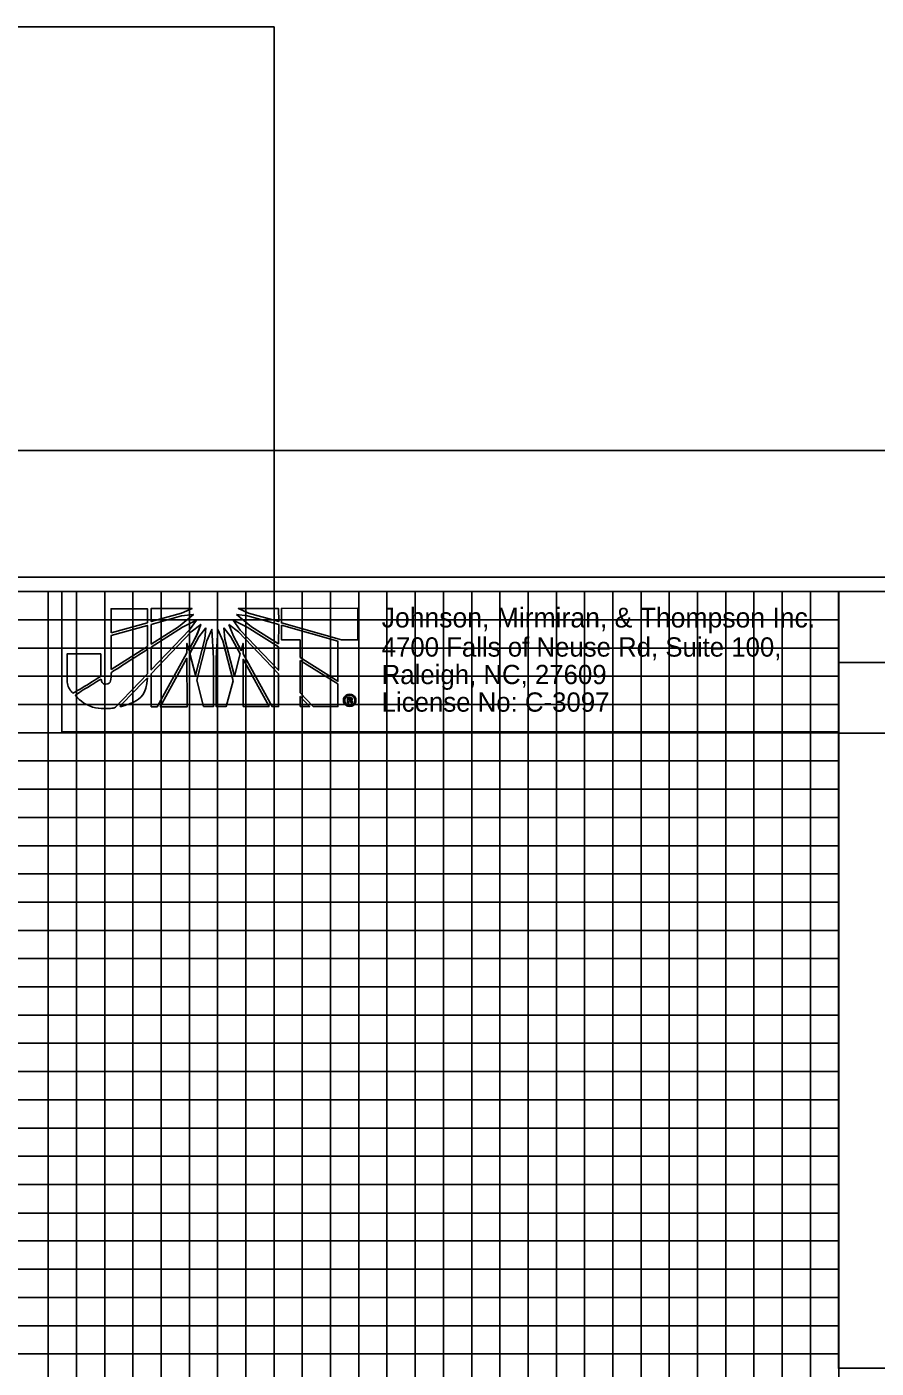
# Model space of a CAD drawing. Extents: x 1621288 to 1629363, y 896995 to 899414.
# Drawn here: x 1628625.6 to 1628776, y 897932.1 to 898169.7 of the extents above; entities that cross this region are included whole.
import ezdxf

# ---------------------------------------------------------------- set-up
doc = ezdxf.new("R2010")
doc.units = 0
for name, color, linetype in [('Default', 7, 'Continuous'), ('Exist Profile Cell', 7, 'Continuous'), ('Exist Structure Minor Pipes CMAP 112inx75in', 7, 'Continuous'), ('Exist Vertical Profile Horizontal Axis Label Major', 7, 'Continuous'), ('Exist XS Ground Line', 7, 'Continuous'), ('Prop Vertical Profile Curve Label', 7, 'Continuous'), ('Prop Vertical Profile Grade', 7, 'Continuous'), ('Prop VPI Label', 7, 'Continuous'), ('Sheet Layout Plan Border', 7, 'Continuous'), ('Sheet Layout Profile Border', 7, 'Continuous'), ('Sheet Layout Profile Border Port 2', 7, 'Continuous')]:
    doc.layers.add(name, color=color, linetype=linetype)

msp = doc.modelspace()

# ---------------------------------------------------------------- linework, layer by layer
at = {"layer": 'Default'}
for p, q in [((1628646.95, 898066.62), (1628640.51, 898066.62)), ((1628640.51, 898066.62), (1628640.51, 898062.35)), ((1628646.95, 898064.14), (1628646.95, 898066.62)), ((1628654.86, 898066.66), (1628647.61, 898066.65)), ((1628647.61, 898066.65), (1628647.62, 898064.35)), ((1628647.62, 898064.35), (1628653.01, 898065.84)), ((1628652.45, 898063.43), (1628655.11, 898065.6)), ((1628653.01, 898065.84), (1628654.86, 898066.66)), ((1628655.11, 898065.6), (1628653.01, 898065.34)), ((1628662.7, 898065.6), (1628665.4, 898063.4)), ((1628664.68, 898065.35), (1628662.7, 898065.6)), ((1628670.19, 898066.64), (1628663.06, 898066.67)), ((1628663.06, 898066.67), (1628664.86, 898065.82)), ((1628664.86, 898065.82), (1628670.2, 898064.33)), ((1628670.2, 898064.33), (1628670.19, 898066.64)), ((1628684.22, 898066.69), (1628670.69, 898066.67)), ((1628670.69, 898066.67), (1628670.69, 898064.19)), ((1628684.23, 898061.14), (1628684.22, 898066.69)), ((1628640.51, 898062.35), (1628646.95, 898064.14)), ((1628646.95, 898063.67), (1628640.51, 898061.86)), ((1628646.95, 898059.94), (1628646.95, 898063.67)), ((1628653.01, 898065.34), (1628647.62, 898063.85)), ((1628647.62, 898063.85), (1628647.62, 898060.37)), ((1628647.62, 898060.37), (1628652.45, 898063.43)), ((1628653.19, 898063.36), (1628647.62, 898059.8)), ((1628655.65, 898064.6), (1628653.19, 898063.36)), ((1628654.4, 898062.86), (1628655.65, 898064.6)), ((1628656.39, 898063.83), (1628654.68, 898062.51)), ((1628655.61, 898061.76), (1628656.39, 898063.83)), ((1628657.31, 898063.25), (1628656.04, 898061.62)), ((1628657.13, 898061.27), (1628657.31, 898063.25)), ((1628660.47, 898063.26), (1628660.68, 898061.2)), ((1628661.71, 898061.62), (1628660.47, 898063.26)), ((1628661.38, 898063.83), (1628662.17, 898061.77)), ((1628663.09, 898062.51), (1628661.38, 898063.83)), ((1628662.13, 898064.61), (1628663.38, 898062.83)), ((1628664.62, 898063.37), (1628662.13, 898064.61)), ((1628670.16, 898059.85), (1628664.62, 898063.37)), ((1628670.2, 898063.84), (1628664.68, 898065.35)), ((1628665.4, 898063.4), (1628670.16, 898060.43)), ((1628670.16, 898060.43), (1628670.2, 898063.84)), ((1628670.69, 898064.19), (1628670.69, 898064.11)), ((1628670.69, 898064.11), (1628681.35, 898061.14)), ((1628670.69, 898063.73), (1628670.69, 898063.69)), ((1628680.67, 898060.89), (1628670.69, 898063.73)), ((1628670.69, 898063.69), (1628670.7, 898061.1)), ((1628640.51, 898061.86), (1628640.52, 898055.86)), ((1628647.62, 898055.79), (1628654.4, 898062.86)), ((1628654.68, 898062.51), (1628647.62, 898055.11)), ((1628654.26, 898059.31), (1628655.61, 898061.76)), ((1628656.04, 898061.62), (1628654.44, 898058.71)), ((1628655.47, 898054.84), (1628657.13, 898061.27)), ((1628657.5, 898060.91), (1628655.69, 898053.95)), ((1628658.38, 898062.97), (1628657.5, 898060.91)), ((1628658.66, 898057.89), (1628658.38, 898062.97)), ((1628659.44, 898062.97), (1628659.11, 898057.89)), ((1628660.29, 898060.91), (1628659.44, 898062.97)), ((1628662.14, 898053.85), (1628660.29, 898060.91)), ((1628660.68, 898061.2), (1628662.35, 898054.7)), ((1628663.38, 898058.61), (1628661.71, 898061.62)), ((1628662.17, 898061.77), (1628663.55, 898059.21)), ((1628670.16, 898055.07), (1628663.09, 898062.51)), ((1628663.38, 898062.83), (1628670.16, 898055.73)), ((1628670.7, 898061.1), (1628674, 898061.1)), ((1628674, 898061.1), (1628674, 898058.01)), ((1628680.68, 898053.79), (1628680.67, 898060.89)), ((1628681.35, 898061.14), (1628684.23, 898061.14)), ((1628640.52, 898055.86), (1628646.95, 898059.94)), ((1628647.62, 898059.8), (1628647.62, 898055.79)), ((1628648.69, 898049.27), (1628653.94, 898058.78)), ((1628653.94, 898058.78), (1628653.94, 898060.48)), ((1628653.94, 898060.48), (1628654.26, 898059.31)), ((1628654.44, 898058.71), (1628655.47, 898054.84)), ((1628662.35, 898054.7), (1628663.38, 898058.61)), ((1628663.55, 898059.21), (1628663.88, 898060.49)), ((1628663.88, 898060.49), (1628663.88, 898058.61)), ((1628663.88, 898058.61), (1628669.03, 898049.29)), ((1628670.16, 898055.73), (1628670.16, 898059.85)), ((1628653.94, 898057.86), (1628649.19, 898049.27)), ((1628653.99, 898049.27), (1628653.94, 898057.86)), ((1628658.66, 898049.31), (1628658.66, 898057.89)), ((1628659.11, 898057.89), (1628659.12, 898049.31)), ((1628668.5, 898049.32), (1628663.88, 898057.68)), ((1628663.88, 898057.68), (1628663.89, 898049.31)), ((1628674, 898058.01), (1628680.68, 898053.79)), ((1628674, 898057.48), (1628674.01, 898051.72)), ((1628680.68, 898053.29), (1628674, 898057.48)), ((1628647.62, 898055.11), (1628647.63, 898049.27)), ((1628655.69, 898053.95), (1628656.9, 898049.31)), ((1628660.9, 898049.31), (1628662.14, 898053.85)), ((1628670.17, 898049.29), (1628670.16, 898055.07)), ((1628674.01, 898051.72), (1628676.31, 898049.29)), ((1628680.68, 898049.3), (1628680.68, 898053.29)), ((1628682.77, 898051.47), (1628682.77, 898051.27)), ((1628682.77, 898051.27), (1628682.77, 898051.47)), ((1628647.63, 898049.27), (1628648.69, 898049.27)), ((1628649.19, 898049.27), (1628653.99, 898049.27)), ((1628656.9, 898049.31), (1628658.66, 898049.31)), ((1628659.12, 898049.31), (1628660.9, 898049.31)), ((1628663.89, 898049.31), (1628668.5, 898049.32)), ((1628669.03, 898049.29), (1628670.17, 898049.29)), ((1628675.68, 898049.29), (1628674.01, 898051.1)), ((1628674.01, 898051.1), (1628674.01, 898049.29)), ((1628674.01, 898049.29), (1628675.68, 898049.29)), ((1628676.31, 898049.29), (1628680.68, 898049.3)), ((1628682.37, 898049.91), (1628682.37, 898050.89)), ((1628682.37, 898050.89), (1628682.78, 898050.89)), ((1628682.6, 898049.91), (1628682.37, 898049.91)), ((1628682.78, 898050.7), (1628682.6, 898050.7)), ((1628682.6, 898050.7), (1628682.6, 898050.47)), ((1628682.6, 898050.47), (1628682.78, 898050.47)), ((1628682.78, 898050.29), (1628682.6, 898050.29)), ((1628682.6, 898050.29), (1628682.6, 898049.91)), ((1628682.78, 898050.89), (1628682.78, 898050.7)), ((1628682.78, 898050.7), (1628682.78, 898050.89)), ((1628682.78, 898050.89), (1628682.84, 898050.89)), ((1628682.8, 898050.7), (1628682.78, 898050.7)), ((1628682.78, 898050.47), (1628682.78, 898050.29)), ((1628682.78, 898050.29), (1628682.78, 898050.47)), ((1628682.78, 898050.47), (1628682.78, 898050.47)), ((1628682.78, 898050.29), (1628682.78, 898050.29)), ((1628682.78, 898049.52), (1628682.78, 898049.31)), ((1628682.78, 898049.31), (1628682.78, 898049.52)), ((1628682.78, 898049.52), (1628682.79, 898049.52)), ((1628682.79, 898049.31), (1628682.78, 898049.31))]:
    msp.add_line(p, q, dxfattribs=at)
for points in [[(1628631.8, 898044.84), (1628769.33, 898044.83), (1628769.33, 898069.65), (1628631.81, 898069.66)], [(1628663.06, 898066.67), (1628670.19, 898066.64), (1628670.2, 898064.33), (1628664.86, 898065.82)], [(1628647.63, 898049.27), (1628647.62, 898055.11), (1628654.68, 898062.51), (1628656.39, 898063.83), (1628655.82, 898062.2), (1628654.26, 898059.31), (1628653.94, 898060.48), (1628653.94, 898058.78), (1628648.69, 898049.27)]]:
    msp.add_lwpolyline(points, close=True, dxfattribs=at)
for points in [[(1628640.51, 898062.35), (1628646.95, 898064.14), (1628646.95, 898066.62), (1628640.51, 898066.62), (1628640.51, 898062.35)], [(1628653.01, 898065.84), (1628654.86, 898066.66), (1628647.61, 898066.65), (1628647.62, 898064.35), (1628653.01, 898065.84)], [(1628647.62, 898063.85), (1628647.62, 898060.37), (1628652.45, 898063.43), (1628655.11, 898065.6), (1628653.01, 898065.34), (1628647.62, 898063.85)], [(1628662.7, 898065.6), (1628665.4, 898063.4), (1628670.16, 898060.43), (1628670.2, 898063.84), (1628664.68, 898065.35), (1628662.7, 898065.6)], [(1628664.86, 898065.82), (1628670.2, 898064.33), (1628670.19, 898066.64), (1628663.06, 898066.67), (1628664.86, 898065.82)], [(1628684.22, 898066.69), (1628670.69, 898066.67), (1628670.69, 898064.19), (1628670.69, 898064.11), (1628681.35, 898061.14), (1628684.23, 898061.14), (1628684.22, 898066.69)], [(1628640.52, 898055.86), (1628646.95, 898059.94), (1628646.95, 898063.67), (1628640.51, 898061.86), (1628640.52, 898055.86)], [(1628647.62, 898059.8), (1628647.62, 898055.79), (1628654.4, 898062.86), (1628655.65, 898064.6), (1628653.19, 898063.36), (1628647.62, 898059.8)], [(1628656.39, 898063.83), (1628654.68, 898062.51), (1628647.62, 898055.11), (1628647.63, 898049.27), (1628648.69, 898049.27), (1628653.94, 898058.78), (1628653.94, 898060.48), (1628654.26, 898059.31), (1628655.61, 898061.76), (1628656.39, 898063.83)], [(1628657.31, 898063.25), (1628656.04, 898061.62), (1628654.44, 898058.71), (1628655.47, 898054.84), (1628657.13, 898061.27), (1628657.31, 898063.25)], [(1628660.47, 898063.26), (1628660.68, 898061.2), (1628662.35, 898054.7), (1628663.38, 898058.61), (1628661.71, 898061.62), (1628660.47, 898063.26)], [(1628661.38, 898063.83), (1628662.17, 898061.77), (1628663.55, 898059.21), (1628663.88, 898060.49), (1628663.88, 898058.61), (1628669.03, 898049.29), (1628670.17, 898049.29), (1628670.16, 898055.07), (1628663.09, 898062.51), (1628661.38, 898063.83)], [(1628662.13, 898064.61), (1628663.38, 898062.83), (1628670.16, 898055.73), (1628670.16, 898059.85), (1628664.62, 898063.37), (1628662.13, 898064.61)], [(1628670.69, 898063.73), (1628670.69, 898063.69), (1628670.7, 898061.1), (1628674, 898061.1), (1628674, 898058.01), (1628680.68, 898053.79), (1628680.67, 898060.89), (1628670.69, 898063.73)], [(1628657.5, 898060.91), (1628655.69, 898053.95), (1628656.9, 898049.31), (1628658.66, 898049.31), (1628658.66, 898057.89), (1628658.38, 898062.97), (1628657.5, 898060.91)], [(1628659.44, 898062.97), (1628659.11, 898057.89), (1628659.12, 898049.31), (1628660.9, 898049.31), (1628662.14, 898053.85), (1628660.29, 898060.91), (1628659.44, 898062.97)], [(1628649.19, 898049.27), (1628653.99, 898049.27), (1628653.94, 898057.86), (1628649.19, 898049.27)], [(1628663.89, 898049.31), (1628668.5, 898049.32), (1628663.88, 898057.68), (1628663.89, 898049.31)], [(1628674, 898057.48), (1628674.01, 898051.72), (1628676.31, 898049.29), (1628680.68, 898049.3), (1628680.68, 898053.29), (1628674, 898057.48), (1628674, 898057.48)], [(1628674.01, 898049.29), (1628674.01, 898049.29), (1628675.68, 898049.29), (1628674.01, 898051.1), (1628674.01, 898049.29)], [(1628683.21, 898050.14), (1628683.21, 898050.09), (1628683.21, 898050.05), (1628683.21, 898050.01), (1628683.24, 898049.91), (1628683.04, 898049.91)]]:
    msp.add_lwpolyline(points, dxfattribs=at)
for points, degree in [([(1628638.67, 898058.62), (1628638.67, 898058.62), (1628632.71, 898058.61), (1628632.71, 898058.61), (1628632.71, 898058.61), (1628632.71, 898054.88), (1628632.71, 898054.88), (1628632.71, 898054.88), (1628632.71, 898054.49), (1628632.71, 898054.49), (1628632.72, 898053.32), (1628633.1, 898052.4), (1628633.78, 898051.62), (1628633.78, 898051.62), (1628638.67, 898054.6), (1628638.67, 898054.68), (1628638.67, 898054.68), (1628638.67, 898058.62), (1628638.67, 898058.62)], 3), ([(1628639.6, 898053.25), (1628639.21, 898053.25), (1628638.89, 898053.47), (1628638.75, 898054.18), (1628638.75, 898054.18), (1628634.13, 898051.32), (1628634.13, 898051.32), (1628635.55, 898049.82), (1628637.83, 898048.93), (1628639.75, 898048.93), (1628640.25, 898048.93), (1628640.63, 898048.98), (1628641.16, 898049.08), (1628641.16, 898049.08), (1628646.96, 898055.08), (1628646.96, 898055.08), (1628646.96, 898055.08), (1628646.95, 898059.41), (1628646.95, 898059.41), (1628646.95, 898059.41), (1628640.52, 898055.32), (1628640.52, 898055.32), (1628640.52, 898053.69), (1628640.13, 898053.26), (1628639.6, 898053.25)], 3), ([(1628639.6, 898053.25), (1628639.21, 898053.25), (1628638.89, 898053.47), (1628638.75, 898054.18), (1628638.75, 898054.18), (1628634.13, 898051.32), (1628634.13, 898051.32), (1628635.55, 898049.82), (1628637.83, 898048.93), (1628639.75, 898048.93), (1628640.25, 898048.93), (1628640.63, 898048.98), (1628641.16, 898049.08), (1628641.16, 898049.08), (1628646.96, 898055.08), (1628646.96, 898055.08), (1628646.96, 898055.08), (1628646.95, 898059.41), (1628646.95, 898059.41), (1628646.95, 898059.41), (1628640.52, 898055.32), (1628640.52, 898055.32), (1628640.52, 898053.69), (1628640.13, 898053.26), (1628639.6, 898053.25)], 3), ([(1628646.96, 898054.4), (1628646.96, 898054.4), (1628641.95, 898049.22), (1628641.95, 898049.22), (1628644.4, 898049.83), (1628646.84, 898051.46), (1628646.96, 898054.4)], 3), ([(1628682.78, 898049.31), (1628682.48, 898049.31), (1628682.22, 898049.41), (1628682.01, 898049.63), (1628681.79, 898049.83), (1628681.68, 898050.09), (1628681.68, 898050.4), (1628681.68, 898050.7), (1628681.79, 898050.96), (1628682.01, 898051.16), (1628682.22, 898051.36), (1628682.47, 898051.47), (1628682.77, 898051.47)], 3), ([(1628682.77, 898051.47), (1628683.08, 898051.47), (1628683.34, 898051.36), (1628683.55, 898051.16), (1628683.77, 898050.96), (1628683.88, 898050.7), (1628683.88, 898050.4)], 3), ([(1628682.77, 898051.27), (1628682.53, 898051.27), (1628682.33, 898051.18), (1628682.16, 898051.02), (1628681.99, 898050.85), (1628681.9, 898050.64), (1628681.9, 898050.4), (1628681.9, 898050.16), (1628681.99, 898049.94), (1628682.16, 898049.77), (1628682.33, 898049.6), (1628682.53, 898049.52), (1628682.78, 898049.52)], 3), ([(1628682.79, 898049.52), (1628683.03, 898049.52), (1628683.23, 898049.6), (1628683.4, 898049.77), (1628683.57, 898049.94), (1628683.66, 898050.16), (1628683.66, 898050.4), (1628683.66, 898050.64), (1628683.57, 898050.85), (1628683.4, 898051.02), (1628683.23, 898051.19), (1628683.03, 898051.27), (1628682.77, 898051.27)], 3), ([(1628682.78, 898050.47), (1628682.93, 898050.47), (1628683, 898050.51), (1628683, 898050.6), (1628683, 898050.67), (1628682.94, 898050.7), (1628682.8, 898050.7)], 3), ([(1628682.95, 898050.26), (1628682.93, 898050.27), (1628682.87, 898050.29), (1628682.78, 898050.29)], 2), ([(1628683.88, 898050.4), (1628683.88, 898050.09), (1628683.77, 898049.84), (1628683.56, 898049.62), (1628683.35, 898049.41), (1628683.09, 898049.31), (1628682.79, 898049.31)], 3), ([(1628682.84, 898050.89), (1628683.09, 898050.89), (1628683.21, 898050.79), (1628683.21, 898050.6), (1628683.21, 898050.51), (1628683.18, 898050.43), (1628683.1, 898050.38)], 3), ([(1628683.04, 898049.91), (1628683.01, 898049.96), (1628682.99, 898050.01), (1628682.99, 898050.09), (1628682.99, 898050.17), (1628682.98, 898050.23), (1628682.95, 898050.26)], 3), ([(1628683.1, 898050.38), (1628683.16, 898050.34), (1628683.2, 898050.26), (1628683.21, 898050.14)], 2)]:
    msp.add_open_spline(points, degree=degree, dxfattribs=at)
at = {"layer": 'Exist Profile Cell'}
for p, q in [((1627519.38, 898064.66), (1628769.38, 898064.66)), ((1628769.38, 898059.66), (1627519.38, 898059.31)), ((1627519.38, 898054.66), (1628769.38, 898054.66)), ((1628769.33, 897934.66), (1627519.38, 897934.66))]:
    msp.add_line(p, q, dxfattribs=at)
for points in [[(1628624.38, 897569.66), (1628629.38, 897569.66), (1628629.38, 898069.66), (1628634.38, 898069.66), (1628634.38, 897569.66), (1628639.38, 897569.66), (1628639.38, 898069.66), (1628649.38, 898069.66), (1628649.38, 897569.66), (1628654.38, 897569.66), (1628654.38, 898069.66), (1628659.38, 898069.66), (1628659.38, 897569.66)], [(1628664.38, 897569.66), (1628664.38, 898069.66), (1628674.38, 898069.66), (1628674.38, 897569.66)], [(1628679.38, 897569.66), (1628679.38, 898069.66), (1628684.38, 898069.66), (1628684.38, 897569.66)], [(1628689.38, 897569.66), (1628689.38, 898069.66), (1628699.38, 898069.66), (1628699.38, 897569.66)], [(1628704.38, 897569.66), (1628704.38, 898069.66), (1628709.38, 898069.66), (1628709.38, 897569.66)], [(1628714.38, 897569.66), (1628714.38, 898069.66), (1628724.38, 898069.66), (1628724.38, 897569.66)], [(1628729.38, 897569.66), (1628729.38, 898069.66), (1628734.38, 898069.66), (1628734.38, 897569.66)], [(1628739.38, 897569.66), (1628739.38, 898069.66), (1628749.38, 898069.66), (1628749.38, 897569.66)], [(1628754.38, 897569.66), (1628754.38, 898069.66), (1628759.38, 898069.66), (1628759.38, 897569.66)], [(1628764.38, 897569.66), (1628764.38, 898069.66), (1628774.38, 898069.66)], [(1628769.38, 898049.66), (1627519.38, 898049.66), (1627519.38, 898039.66), (1628769.38, 898039.66)], [(1628769.33, 898034.66), (1627519.38, 898034.66), (1627519.38, 898029.66), (1628769.38, 898029.66)], [(1628769.38, 898024.66), (1627519.38, 898024.66), (1627519.38, 898014.66), (1628769.38, 898014.66)], [(1628769.38, 898009.66), (1627519.38, 898009.66), (1627519.38, 898004.66), (1628769.38, 898004.66)], [(1628769.38, 897999.66), (1627519.38, 897999.66), (1627519.38, 897989.66), (1628769.38, 897989.66)], [(1628769.38, 897984.66), (1627519.38, 897984.66), (1627519.38, 897979.66), (1628769.38, 897979.66)], [(1628769.38, 897974.66), (1627519.38, 897974.66), (1627519.38, 897964.66), (1628769.38, 897964.66)], [(1628769.38, 897959.56), (1627519.48, 897959.56), (1627519.48, 897954.66), (1628769.38, 897954.66)], [(1628769.38, 897949.66), (1627519.38, 897949.66), (1627519.38, 897939.66), (1628769.38, 897939.66)]]:
    msp.add_lwpolyline(points, dxfattribs=at)
at = {"layer": 'Exist Structure Minor Pipes CMAP 112inx75in'}
msp.add_lwpolyline([(1628314.38, 898169.66), (1628669.38, 898169.66), (1628669.38, 897764.66), (1628314.38, 897764.66)], close=True, dxfattribs=at)
at = {"layer": 'Exist Vertical Profile Horizontal Axis Label Major'}
msp.add_lwpolyline([(1628631.8, 898069.66), (1628769.33, 898069.66), (1628769.33, 898044.83), (1628631.8, 898044.83)], close=True, dxfattribs=at)
at = {"layer": 'Exist XS Ground Line'}
msp.add_line((1628769.33, 898057.11), (1628969.38, 898057.11), dxfattribs=at)
for points in [[(1628969.38, 898069.66), (1627469.38, 898069.66), (1627469.38, 897019.66), (1628969.38, 897019.66)], [(1628769.33, 898069.66), (1628969.38, 898069.66), (1628969.38, 898044.61), (1628769.33, 898044.61)], [(1628769.33, 898044.61), (1628869.38, 898044.61), (1628869.38, 897932.11), (1628769.33, 897932.11)]]:
    msp.add_lwpolyline(points, close=True, dxfattribs=at)
at = {"layer": 'Prop Vertical Profile Curve Label'}
msp.add_lwpolyline([(1627315.38, 897017.11), (1628981.88, 897017.11), (1628981.88, 898072.21), (1627315.38, 898072.21)], close=True, dxfattribs=at)
at = {"layer": 'Prop Vertical Profile Grade'}
msp.add_line((1627469.38, 898044.66), (1628769.33, 898044.66), dxfattribs=at)
for points in [[(1628244.38, 897569.66), (1628294.38, 897569.66), (1628294.38, 898069.66), (1628344.38, 898069.66), (1628344.38, 897569.66), (1628394.38, 897569.66), (1628394.38, 898069.66), (1628444.38, 898069.66), (1628444.38, 897569.66), (1628494.38, 897569.66), (1628494.38, 898069.66), (1628544.38, 898069.66), (1628544.38, 897569.66), (1628594.38, 897569.66), (1628594.38, 898069.66), (1628644.38, 898069.66), (1628644.38, 897569.66), (1628694.38, 897569.66), (1628694.38, 898069.66), (1628744.38, 898069.66), (1628744.38, 897569.66), (1628794.38, 897569.66), (1628794.38, 897908.61)], [(1628769.38, 897994.66), (1627469.38, 897994.66), (1627469.38, 897944.66), (1628769.38, 897944.66)]]:
    msp.add_lwpolyline(points, dxfattribs=at)
at = {"layer": 'Prop VPI Label'}
for points in [[(1628269.38, 898069.66), (1628319.38, 898069.66), (1628319.38, 897569.66), (1628369.38, 897569.66), (1628369.38, 898069.66), (1628419.38, 898069.66), (1628419.38, 897569.66), (1628469.38, 897569.66), (1628469.38, 898069.66), (1628519.38, 898069.66), (1628519.38, 897569.66), (1628569.38, 897569.66), (1628569.38, 898069.66), (1628619.38, 898069.66), (1628619.38, 897569.66), (1628669.38, 897569.66), (1628669.38, 898069.66), (1628719.38, 898069.66), (1628719.38, 897569.66), (1628769.38, 897569.66), (1628769.38, 898069.66), (1628795.68, 898069.66)], [(1627469.38, 898019.66), (1628769.38, 898019.66)], [(1628769.38, 897969.66), (1627469.38, 897969.66), (1627469.38, 897919.66), (1628769.38, 897919.66)]]:
    msp.add_lwpolyline(points, dxfattribs=at)
at = {"layer": 'Sheet Layout Plan Border'}
msp.add_lwpolyline([(1627302.38, 896994.66), (1628986.38, 896994.66), (1628986.38, 898094.66), (1627302.38, 898094.66)], close=True, dxfattribs=at)
at = {"layer": 'Sheet Layout Profile Border'}
msp.add_line((1628986.38, 898094.66), (1627302.38, 898094.66), dxfattribs=at)
at = {"layer": 'Sheet Layout Profile Border Port 2'}
for p, q in [((1628669.38, 897569.66), (1628669.38, 898069.66)), ((1628719.38, 897569.66), (1628719.38, 898069.66)), ((1628769.33, 898019.66), (1627469.38, 898019.66)), ((1628769.33, 897969.66), (1627469.38, 897969.66))]:
    msp.add_line(p, q, dxfattribs=at)

# ---------------------------------------------------------------- texts
at = {"layer": 'Default'}
for s, height, p in [('Johnson, Mirmiran, & Thompson Inc.', 3.5139, (1628688.44, 898063.3)), ('4700 Falls of Neuse Rd, Suite 100, ', 3.4135, (1628688.44, 898058.14)), ('Raleigh, NC, 27609', 3.4135, (1628688.44, 898053.27)), ('License No: C-3097', 3.4135, (1628688.44, 898048.39))]:
    msp.add_text(s, height=height, rotation=359.9946, dxfattribs=at).set_placement(p)

doc.saveas('drawing.dxf')
